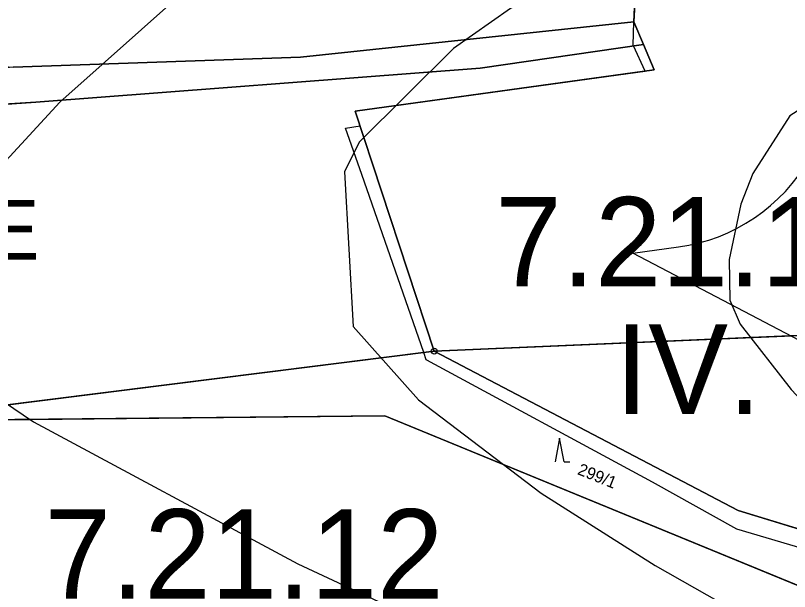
# Model space of a CAD drawing. Extents: x -706130 to -698555, y -971544 to -967260.
# Drawn here: x -703632.5 to -703502.6, y -970191.3 to -970094.6 of the extents above; entities that cross this region are included whole.
import ezdxf

# ---------------------------------------------------------------- set-up
doc = ezdxf.new("R2010")
doc.units = 0
for name, color, linetype in [('BPEJ hranice S', 7, 'Continuous'), ('BPEJ kód', 7, 'Continuous'), ('Docházková izochrona - VLAK N', 7, 'Continuous'), ('KN_Hranice_parcel', 7, 'Continuous'), ('KN_Parcelni cisla', 7, 'Continuous'), ('KN_Polygon parcely', 7, 'Continuous'), ('KN_POZEMKY_10_LESNI POZEMEK', 7, 'Continuous'), ('KN_POZEMKY_14_OSTATNI PLOCHA', 7, 'Continuous'), ('KN_POZEMKY_2_ORNA PUDA', 7, 'Continuous'), ('KN_POZEMKY_7_TTP', 7, 'Continuous'), ('KN_VYUZITI_17_ostatni plocha_ostatni komunikace', 7, 'Continuous'), ('KN_Značky bodu BP', 7, 'Continuous'), ('KN_Značky kultur', 7, 'Continuous'), ('OP lesa 30 m', 7, 'Continuous'), ('Plochy lesní všeobecné S', 7, 'Continuous'), ('Plochy smíšené nezastavěného území všeobecné S', 7, 'Continuous'), ('Plochy zemědělské všeobecné CELEK S', 7, 'Continuous'), ('Regulační bloky v krajině S', 7, 'Continuous'), ('Regulační kódy v krajině S', 7, 'Continuous'), ('VÝŠKOPIS_vrstevnice hlavní', 7, 'Continuous'), ('VÝŠKOPIS_vrstevnice zesílená', 7, 'Continuous')]:
    doc.layers.add(name, color=color, linetype=linetype)

msp = doc.modelspace()

# ---------------------------------------------------------------- linework, layer by layer
at = {"layer": 'BPEJ hranice S'}
for points in [[(-703467.54, -970193.77), (-703511.44, -970180.82), (-703525.62, -970172.94), (-703563.48, -970152.43), (-703563.55, -970152.4), (-703563.98, -970151.16), (-703574.39, -970121.33), (-703577.1, -970113.55), (-703574.65, -970113.17), (-703575.47, -970110.67), (-703526.82, -970103.96), (-703528.79, -970099.76), (-703528.85, -970099.62), (-703528.72, -970095.73), (-703584.65, -970101.63), (-703632.86, -970103.3)], [(-703712.99, -970194.37), (-703721.04, -970175.78), (-703722.8, -970171.56), (-703731.27, -970151.3), (-703734.78, -970144.43), (-703738.39, -970137.36), (-703738.39, -970127.59), (-703738.39, -970126.43), (-703732.05, -970125.35), (-703711.68, -970121.88), (-703709.95, -970121.51), (-703701.37, -970168.64), (-703701.97, -970168.73), (-703701.95, -970168.81), (-703713.92, -970170.95), (-703707.62, -970182.89), (-703660.48, -970173.94), (-703659.47, -970172), (-703655.23, -970162.65), (-703570.53, -970161.82), (-703450.72, -970210.98)]]:
    msp.add_lwpolyline(points, dxfattribs=at)
at = {"layer": 'Docházková izochrona - VLAK N'}
msp.add_circle((-704165.45, -969778.77), 800, dxfattribs=at)
at = {"layer": 'KN_Hranice_parcel'}
for p, q in [((-703528.72, -970095.73), (-703527.23, -970062.71)), ((-703527.12, -970099.52), (-703528.72, -970095.73)), ((-703420.94, -970144.86), (-703562.22, -970150.94)), ((-703562.22, -970150.94), (-703655.23, -970162.65))]:
    msp.add_line(p, q, dxfattribs=at)
for points in [[(-703632.86, -970103.3), (-703584.65, -970101.63), (-703528.72, -970095.73)], [(-703709.95, -970121.51), (-703667.12, -970112.26), (-703655.52, -970110.86), (-703629.06, -970109.21), (-703554.49, -970103.46), (-703527.12, -970099.52)], [(-703527.12, -970099.52), (-703525.33, -970103.75), (-703575.47, -970110.67), (-703562.22, -970150.94)], [(-703562.22, -970150.94), (-703511.23, -970177.68), (-703468.7, -970190.64), (-703434.36, -970196.61), (-703430.72, -970200.4), (-703431.33, -970215.29), (-703450.72, -970210.98), (-703570.53, -970161.82), (-703655.23, -970162.65)]]:
    msp.add_lwpolyline(points, dxfattribs=at)
at = {"layer": 'KN_Polygon parcely'}
for points in [[(-703059.96, -970234.42), (-703048.81, -970203.91), (-703040.22, -970170.64), (-703042.42, -970149.39), (-703035.09, -970122.78), (-703084.29, -970113.47), (-703214.07, -970078.16), (-703330.9, -970049.16), (-703395.77, -970043.37), (-703447.56, -970051.49), (-703527.23, -970062.71), (-703528.72, -970095.73), (-703527.12, -970099.52), (-703525.33, -970103.75), (-703575.47, -970110.67), (-703562.22, -970150.94), (-703420.94, -970144.86), (-703371.96, -970147.76), (-703264.02, -970171.01), (-703179.97, -970194.21), (-703103.1, -970216.61)], [(-703528.72, -970095.73), (-703527.23, -970062.71), (-703533.48, -970063.59), (-703645.23, -970073.63), (-703658.73, -970074.83), (-703741.2, -970085.2), (-703737.12, -970119.68), (-703702.23, -970112.19), (-703669.08, -970100.67), (-703632.86, -970103.3), (-703584.65, -970101.63)], [(-703527.12, -970099.52), (-703528.72, -970095.73), (-703584.65, -970101.63), (-703632.86, -970103.3), (-703668.56, -970106.47), (-703701.13, -970115.77), (-703766.62, -970126.02), (-703880.82, -970138.8), (-703959.54, -970148.75), (-703988.89, -970158.47), (-703949.79, -970157.02), (-703792.93, -970137.4), (-703765.94, -970133.47), (-703709.95, -970121.51), (-703667.12, -970112.26), (-703655.52, -970110.86), (-703629.06, -970109.21), (-703554.49, -970103.46)], [(-703701.37, -970168.64), (-703689.89, -970167), (-703655.23, -970162.65), (-703562.22, -970150.94), (-703575.47, -970110.67), (-703525.33, -970103.75), (-703527.12, -970099.52), (-703554.49, -970103.46), (-703629.06, -970109.21), (-703655.52, -970110.86), (-703667.12, -970112.26), (-703709.95, -970121.51)], [(-703562.22, -970150.94), (-703655.23, -970162.65), (-703570.53, -970161.82), (-703450.72, -970210.98), (-703431.33, -970215.29), (-703430.72, -970200.4), (-703434.36, -970196.61), (-703468.7, -970190.64), (-703511.23, -970177.68)]]:
    msp.add_lwpolyline(points, close=True, dxfattribs=at)
msp.add_lwpolyline([(-703103.1, -970216.61), (-703179.97, -970194.21), (-703264.02, -970171.01), (-703371.96, -970147.76), (-703420.94, -970144.86), (-703562.22, -970150.94), (-703511.23, -970177.68), (-703468.7, -970190.64), (-703434.36, -970196.61), (-703430.72, -970200.4), (-703431.33, -970215.29), (-703450.72, -970210.98), (-703570.53, -970161.82), (-703655.23, -970162.65), (-703660.34, -970173.91), (-703707.62, -970182.89), (-703714.1, -970170.6), (-703843.22, -970184.9)], dxfattribs=at)
at = {"layer": 'KN_POZEMKY_10_LESNI POZEMEK'}
for p, q in [((-703554.49, -970103.46), (-703527.12, -970099.52)), ((-703527.12, -970099.52), (-703525.33, -970103.75)), ((-703629.06, -970109.21), (-703554.49, -970103.46)), ((-703525.33, -970103.75), (-703575.47, -970110.67)), ((-703655.52, -970110.86), (-703629.06, -970109.21)), ((-703575.47, -970110.67), (-703562.22, -970150.94)), ((-703655.23, -970162.65), (-703562.22, -970150.94)), ((-703562.22, -970150.94), (-703655.23, -970162.65)), ((-703562.22, -970150.94), (-703511.23, -970177.68)), ((-703570.53, -970161.82), (-703655.23, -970162.65)), ((-703450.72, -970210.98), (-703570.53, -970161.82)), ((-703511.23, -970177.68), (-703468.7, -970190.64))]:
    msp.add_line(p, q, dxfattribs=at)
at = {"layer": 'KN_POZEMKY_14_OSTATNI PLOCHA'}
for p, q in [((-703584.65, -970101.63), (-703528.72, -970095.73)), ((-703528.72, -970095.73), (-703527.12, -970099.52)), ((-703527.12, -970099.52), (-703554.49, -970103.46)), ((-703632.86, -970103.3), (-703584.65, -970101.63)), ((-703554.49, -970103.46), (-703629.06, -970109.21)), ((-703629.06, -970109.21), (-703655.52, -970110.86))]:
    msp.add_line(p, q, dxfattribs=at)
at = {"layer": 'KN_POZEMKY_2_ORNA PUDA'}
for p, q in [((-703528.72, -970095.73), (-703527.23, -970062.71)), ((-703527.12, -970099.52), (-703528.72, -970095.73)), ((-703525.33, -970103.75), (-703527.12, -970099.52)), ((-703575.47, -970110.67), (-703525.33, -970103.75)), ((-703562.22, -970150.94), (-703575.47, -970110.67)), ((-703562.22, -970150.94), (-703420.94, -970144.86)), ((-703420.94, -970144.86), (-703562.22, -970150.94)), ((-703511.23, -970177.68), (-703562.22, -970150.94)), ((-703655.23, -970162.65), (-703570.53, -970161.82)), ((-703570.53, -970161.82), (-703450.72, -970210.98)), ((-703468.7, -970190.64), (-703511.23, -970177.68))]:
    msp.add_line(p, q, dxfattribs=at)
at = {"layer": 'KN_POZEMKY_7_TTP'}
for p, q in [((-703527.23, -970062.71), (-703528.72, -970095.73)), ((-703528.72, -970095.73), (-703584.65, -970101.63)), ((-703584.65, -970101.63), (-703632.86, -970103.3))]:
    msp.add_line(p, q, dxfattribs=at)
at = {"layer": 'KN_VYUZITI_17_ostatni plocha_ostatni komunikace'}
for p, q in [((-703584.65, -970101.63), (-703528.72, -970095.73)), ((-703528.72, -970095.73), (-703527.12, -970099.52)), ((-703527.12, -970099.52), (-703554.49, -970103.46)), ((-703632.86, -970103.3), (-703584.65, -970101.63)), ((-703554.49, -970103.46), (-703629.06, -970109.21)), ((-703629.06, -970109.21), (-703655.52, -970110.86))]:
    msp.add_line(p, q, dxfattribs=at)
at = {"layer": 'KN_Značky bodu BP'}
for radius in [0.5, 0.0303]:
    msp.add_circle((-703562.22, -970150.94), radius, dxfattribs=at)
at = {"layer": 'KN_Značky kultur'}
for p, q in [((-703541.2, -970165.53), (-703541.95, -970169.53)), ((-703540.45, -970169.53), (-703541.2, -970165.53)), ((-703540.45, -970169.53), (-703539.45, -970169.53))]:
    msp.add_line(p, q, dxfattribs=at)
at = {"layer": 'OP lesa 30 m'}
msp.add_lwpolyline([(-703429.22, -970167.05), (-703461.73, -970161.4), (-703499.79, -970149.8), (-703528.92, -970134.53), (-703521.23, -970133.47)], dxfattribs=at)
msp.add_arc((-703525.33, -970103.75), 30, 277.858, 22.9365, dxfattribs=at)
at = {"layer": 'Plochy lesní všeobecné S'}
for p, q in [((-703527.12, -970099.52), (-703554.49, -970103.46)), ((-703525.33, -970103.75), (-703527.12, -970099.52)), ((-703554.49, -970103.46), (-703629.06, -970109.21)), ((-703575.47, -970110.67), (-703525.33, -970103.75)), ((-703629.06, -970109.21), (-703655.52, -970110.86)), ((-703562.22, -970150.94), (-703575.47, -970110.67)), ((-703511.23, -970177.68), (-703562.22, -970150.94)), ((-703655.23, -970162.65), (-703570.53, -970161.82)), ((-703570.53, -970161.82), (-703450.72, -970210.98)), ((-703468.7, -970190.64), (-703511.23, -970177.68))]:
    msp.add_line(p, q, dxfattribs=at)
at = {"layer": 'Plochy smíšené nezastavěného území všeobecné S'}
msp.add_line((-703528.72, -970095.73), (-703527.23, -970062.71), dxfattribs=at)
msp.add_lwpolyline([(-703667.12, -970112.26), (-703655.52, -970110.86), (-703629.06, -970109.21), (-703554.49, -970103.46), (-703527.12, -970099.52), (-703528.72, -970095.73)], dxfattribs=at)
at = {"layer": 'Plochy zemědělské všeobecné CELEK S'}
for p, q in [((-703527.23, -970062.71), (-703528.72, -970095.73)), ((-703528.72, -970095.73), (-703527.12, -970099.52)), ((-703527.12, -970099.52), (-703525.33, -970103.75)), ((-703525.33, -970103.75), (-703575.47, -970110.67)), ((-703575.47, -970110.67), (-703562.22, -970150.94)), ((-703562.22, -970150.94), (-703511.23, -970177.68)), ((-703570.53, -970161.82), (-703655.23, -970162.65)), ((-703450.72, -970210.98), (-703570.53, -970161.82)), ((-703511.23, -970177.68), (-703468.7, -970190.64))]:
    msp.add_line(p, q, dxfattribs=at)
at = {"layer": 'Regulační bloky v krajině S'}
for p, q in [((-703528.72, -970095.73), (-703527.23, -970062.71)), ((-703527.23, -970062.71), (-703528.72, -970095.73)), ((-703528.72, -970095.73), (-703527.12, -970099.52)), ((-703527.12, -970099.52), (-703554.49, -970103.46)), ((-703525.33, -970103.75), (-703527.12, -970099.52)), ((-703527.12, -970099.52), (-703525.33, -970103.75)), ((-703554.49, -970103.46), (-703629.06, -970109.21)), ((-703575.47, -970110.67), (-703525.33, -970103.75)), ((-703525.33, -970103.75), (-703575.47, -970110.67)), ((-703629.06, -970109.21), (-703655.52, -970110.86)), ((-703562.22, -970150.94), (-703575.47, -970110.67)), ((-703575.47, -970110.67), (-703562.22, -970150.94)), ((-703511.23, -970177.68), (-703562.22, -970150.94)), ((-703562.22, -970150.94), (-703511.23, -970177.68)), ((-703655.23, -970162.65), (-703570.53, -970161.82)), ((-703570.53, -970161.82), (-703655.23, -970162.65)), ((-703570.53, -970161.82), (-703450.72, -970210.98)), ((-703450.72, -970210.98), (-703570.53, -970161.82)), ((-703468.7, -970190.64), (-703511.23, -970177.68)), ((-703511.23, -970177.68), (-703468.7, -970190.64))]:
    msp.add_line(p, q, dxfattribs=at)
msp.add_lwpolyline([(-703667.12, -970112.26), (-703655.52, -970110.86), (-703629.06, -970109.21), (-703554.49, -970103.46), (-703527.12, -970099.52), (-703528.72, -970095.73)], dxfattribs=at)
at = {"layer": 'VÝŠKOPIS_vrstevnice hlavní'}
for points in [[(-703331.72, -970068.07), (-703359.11, -970070.35), (-703393.35, -970075.35), (-703425.88, -970082.05), (-703444.71, -970087.19), (-703473.25, -970096.18), (-703492.22, -970104.88), (-703502.55, -970111.45), (-703508.77, -970121.15), (-703510.77, -970126.28), (-703512.77, -970135.56), (-703512.63, -970142.4), (-703510.91, -970146.4), (-703502.35, -970157.38), (-703493.08, -970167.23), (-703485.38, -970173.79), (-703477.96, -970178.93), (-703451.85, -970191.34), (-703386.22, -970213.74), (-703360.82, -970221.3), (-703338.85, -970229)], [(-703582.32, -970074.85), (-703604.22, -970090.61), (-703625.05, -970109.16), (-703638.6, -970123.86), (-703642.31, -970130.7), (-703644.17, -970139.84), (-703644.31, -970144.4), (-703640.46, -970153.82), (-703634.47, -970159.38), (-703629.47, -970162.8), (-703585.1, -970186.63), (-703571.55, -970192.91)]]:
    msp.add_lwpolyline(points, dxfattribs=at)
at = {"layer": 'VÝŠKOPIS_vrstevnice zesílená'}
msp.add_lwpolyline([(-703490.42, -970060.22), (-703500.07, -970065.36), (-703549.43, -970093.47), (-703558.99, -970100.17), (-703574.83, -970115.87), (-703577.26, -970120.86), (-703575.83, -970146.83), (-703564.84, -970159.1), (-703544.3, -970174.79), (-703525.18, -970186.92), (-703501.21, -970200.47), (-703493.08, -970202.9)], dxfattribs=at)

# ---------------------------------------------------------------- texts
at = {"layer": 'BPEJ kód'}
for s, p in [('7.21.12', (-703551.98, -970140.1)), ('IV.', (-703531.89, -970161.46)), ('7.21.12', (-703627.58, -970192.45))]:
    msp.add_text(s, height=15, dxfattribs=at).set_placement(p)
at = {"layer": 'KN_Parcelni cisla'}
msp.add_text('299/1', height=2, rotation=338, dxfattribs=at).set_placement((-703538.34, -970171.54))
at = {"layer": 'Regulační kódy v krajině S'}
msp.add_text('LE', height=10, dxfattribs=at).set_placement((-703644.82, -970135.58))

doc.saveas('drawing.dxf')
